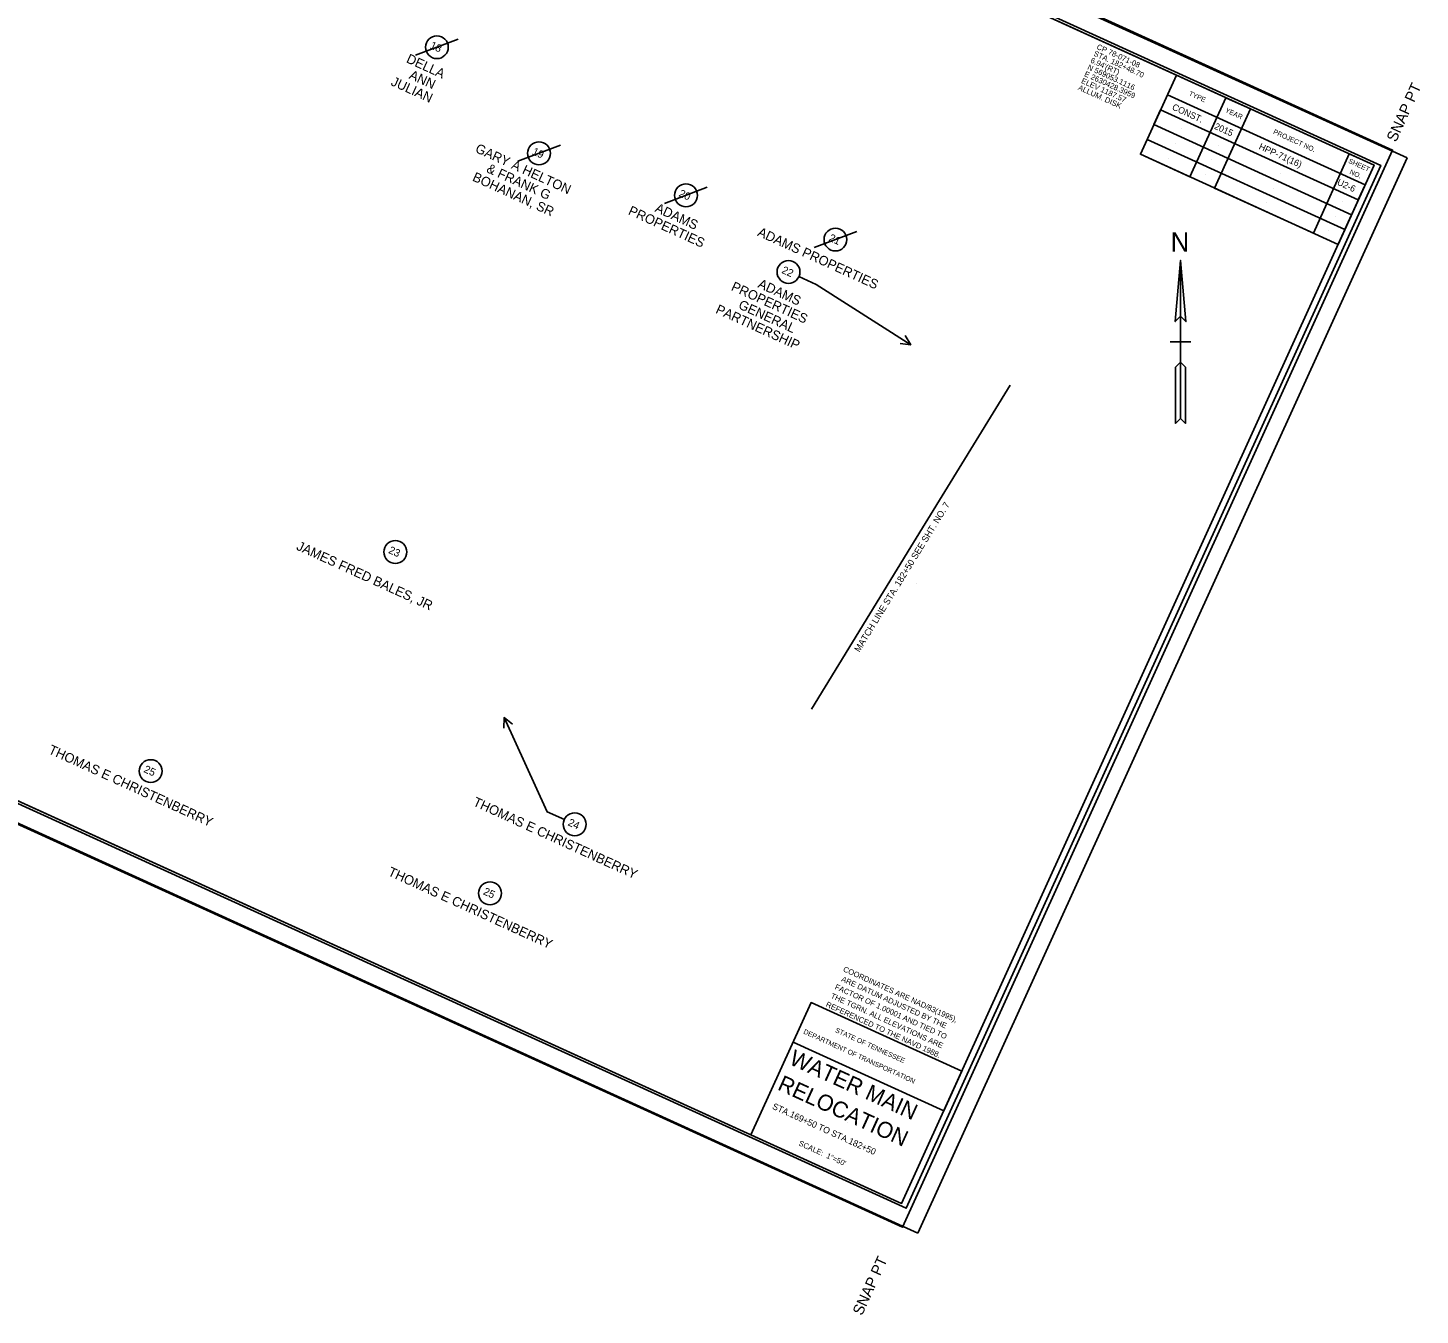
# Model space of a CAD drawing. Extents: x 2628810 to 2630911, y 568379 to 570218.
# Drawn here: x 2629628 to 2630911, y 568379 to 569564 of the extents above; entities that cross this region are included whole.
import ezdxf

# ---------------------------------------------------------------- set-up
doc = ezdxf.new("R2010")
doc.units = 0
for name, color, linetype in [('DESIGN - CENTERLINE - Proposed Text', 7, 'Continuous'), ('DESIGN - SCRATCH - User 1', 7, 'Continuous'), ('DESIGN - SHEET - Corner Text', 7, 'Continuous'), ('DESIGN - SHEET - Light Grid', 7, 'Continuous'), ('DESIGN - SHEET - Linework', 7, 'Continuous'), ('DESIGN - SHEET - Plot Shape', 7, 'Continuous'), ('SURVEY - CONTROL with Text', 7, 'Continuous'), ('SURVEY - PROPERTY - Owners', 7, 'Continuous'), ('SURVEY - PROPERTY - Tract Numbers', 7, 'Continuous')]:
    doc.layers.add(name, color=color, linetype=linetype)

msp = doc.modelspace()

# ---------------------------------------------------------------- linework, layer by layer
at = {"layer": 'DESIGN - CENTERLINE - Proposed Text'}
for p, q in [((2630689.9, 569274.6), (2630680.4, 569274.6)), ((2630699.3, 569274.6), (2630689.9, 569274.6))]:
    msp.add_line(p, q, dxfattribs=at)
for points in [[(2630689.9, 569349.6), (2630685, 569293.3), (2630689.9, 569298.2), (2630694.8, 569293.3), (2630689.9, 569349.6), (2630689.9, 569204.2), (2630694.4, 569199.6), (2630694.4, 569251.4), (2630689.9, 569255.9), (2630685.3, 569251.4), (2630685.3, 569199.6), (2630689.9, 569204.2)], [(2630349.9, 568936.6), (2630441.4, 569085.8), (2630532.9, 569234.9)]]:
    msp.add_lwpolyline(points, dxfattribs=at)
for points in [[(2630689.9, 569298.2), (2630694.8, 569293.3), (2630689.9, 569349.6)], [(2630685.3, 569199.6), (2630689.9, 569204.2), (2630689.9, 569255.9), (2630685.3, 569251.4)]]:
    msp.add_lwpolyline(points, close=True, dxfattribs=at)
at = {"layer": 'DESIGN - SCRATCH - User 1'}
for p, q in [((2630697.4, 569484.7), (2630697.4, 569484.7)), ((2630691.2, 569471.1), (2630691.2, 569471.1)), ((2630731.1, 569469.4), (2630731.1, 569469.4)), ((2630685, 569457.4), (2630685, 569457.4)), ((2630724.9, 569455.7), (2630724.9, 569455.7)), ((2630678.8, 569443.8), (2630678.8, 569443.8)), ((2630718.7, 569442.1), (2630718.7, 569442.1)), ((2630788, 569443.5), (2630788, 569443.5)), ((2630712.4, 569428.4), (2630712.4, 569428.4)), ((2630781.7, 569429.9), (2630781.7, 569429.9)), ((2630775.5, 569416.2), (2630775.5, 569416.2)), ((2630844.8, 569417.6), (2630844.8, 569417.6)), ((2630769.3, 569402.6), (2630769.3, 569402.6)), ((2630838.6, 569404), (2630838.6, 569404)), ((2630832.4, 569390.3), (2630832.4, 569390.3)), ((2630826.2, 569376.7), (2630826.2, 569376.7)), ((2630446.5, 569052.3), (2630446.5, 569052.3)), ((2630383, 568555.8), (2630383, 568555.8))]:
    msp.add_line(p, q, dxfattribs=at)
at = {"layer": 'DESIGN - SHEET - Light Grid'}
msp.add_lwpolyline([(2628921.9, 569166.8), (2630437.2, 568477), (2630874.3, 569437.1), (2629359, 570127)], close=True, dxfattribs=at)
at = {"layer": 'DESIGN - SHEET - Linework'}
for p, q in [((2629260.3, 570189.7), (2630898.6, 569443.9)), ((2630898.6, 569443.9), (2630448, 568454.2)), ((2628809.8, 569200), (2630448, 568454.2))]:
    msp.add_line(p, q, dxfattribs=at)
for points in [[(2629435.3, 570089.5), (2629000.3, 569133.8), (2630433, 568481.6), (2630868.1, 569437.3), (2629435.3, 570089.5)], [(2630686, 569520.1), (2630652.9, 569447.3), (2630834.9, 569364.4), (2630868.1, 569437.3), (2630845.3, 569447.6), (2630812.2, 569374.8), (2630721.2, 569416.2), (2630754.3, 569489), (2630731.6, 569499.4), (2630698.4, 569426.6), (2630652.9, 569447.3), (2630659.1, 569461), (2630841.1, 569378.1), (2630847.4, 569391.7), (2630665.3, 569474.6), (2630671.5, 569488.3), (2630853.6, 569405.4), (2630859.8, 569419.1), (2630677.8, 569501.9)], [(2630294.2, 568544.8), (2630349.6, 568666.4), (2630488.4, 568603.3), (2630471.8, 568566.9), (2630333, 568630)]]:
    msp.add_lwpolyline(points, dxfattribs=at)
at = {"layer": 'DESIGN - SHEET - Plot Shape'}
for points in [[(2629338, 570155.5), (2630885.2, 569451.1), (2630433.8, 568459.6), (2628886.6, 569164)], [(2629357.9, 570124.7), (2630868.1, 569437.3), (2630433, 568481.6), (2628922.9, 569169.1)]]:
    msp.add_lwpolyline(points, close=True, dxfattribs=at)
at = {"layer": 'SURVEY - PROPERTY - Tract Numbers'}
for p, q in [((2629985.3, 569538.5), (2630024.6, 569553.3)), ((2630079.4, 569440.9), (2630118.7, 569455.6)), ((2630214.7, 569402.1), (2630254, 569416.9)), ((2630352.3, 569361.4), (2630391.6, 569376.2))]:
    msp.add_line(p, q, dxfattribs=at)
for points in [[(2630354.3, 569327.4), (2630338.4, 569334.7)], [(2630441.4, 569272), (2630354.3, 569327.4)], [(2630436.4, 569280.4), (2630441.4, 569272), (2630431.7, 569273)], [(2630074.5, 568922.7), (2630066.9, 568928.8), (2630066.5, 568919.1)], [(2630066.9, 568928.8), (2630106.5, 568842.1), (2630122.4, 568834.9)]]:
    msp.add_lwpolyline(points, dxfattribs=at)
for centre in [(2630005, 569545.9), (2630099, 569448.2), (2630234.4, 569409.5), (2630372, 569368.8), (2630328.8, 569339), (2629966.7, 569081.2), (2629741.4, 568879.5), (2630131.9, 568830.5), (2630053.9, 568767)]:
    msp.add_circle(centre, 10.5, dxfattribs=at)

# ---------------------------------------------------------------- texts
at = {"layer": 'DESIGN - CENTERLINE - Proposed Text'}
msp.add_text('N', height=17.7, dxfattribs=at).set_placement((2630680.8, 569357.7))
msp.add_text('MATCH LINE STA. 182+50 SEE SHT. NO. 7', height=6, rotation=58.4832, dxfattribs=at).set_placement((2630394.1, 568988.5))
at = {"layer": 'DESIGN - SHEET - Corner Text'}
for s, height, rotation, p in [('  SNAP PT', 10, 65.5232, (2630885.2, 569451.1)), ('TYPE', 4.5, 335.5232, (2630697.1, 569501.7)), ('CONST.', 6, 335.5232, (2630681.5, 569488.7)), ('YEAR', 4.5, 335.5232, (2630730.5, 569486.3)), ('2015', 6, 335.5232, (2630720.4, 569471)), ('PROJECT NO.', 4.5, 335.5232, (2630774.8, 569466.5)), ('HPP-71(16)', 6, 335.5232, (2630761.4, 569452.3)), ('SHEET', 4.5, 335.5232, (2630844, 569439.6)), ('NO.', 4.5, 335.5232, (2630845.1, 569429.5)), ('U2-6', 6, 335.5232, (2630833.5, 569419.5)), ('ARE DATUM ADJUSTED BY THE', 5, 335.5232, (2630376.9, 568686.3)), ('COORDINATES ARE NAD/83(1995),', 5, 335.5232, (2630378.6, 568695.4)), ('THE TGRN. ALL ELEVATIONS ARE', 5, 335.5232, (2630367.2, 568670.9)), ('FACTOR OF 1.00001 AND TIED TO', 5, 335.5232, (2630371, 568679.1)), ('REFERENCED TO THE NAVD 1988.', 5, 335.5232, (2630362.7, 568663)), ('DEPARTMENT OF TRANSPORTATION', 4.5, 335.5232, (2630342.1, 568638.1)), ('STATE OF TENNESSEE', 4.5, 335.5232, (2630371.4, 568639.4)), ('WATER MAIN', 14.76, 335.5232, (2630328.5, 568610.1)), ('RELOCATION', 14.76, 335.5232, (2630317.8, 568586.6)), ('STA.169+50 TO STA.182+50', 5.906, 335.5232, (2630313.3, 568568.8)), ('SCALE:  1"=50\'', 4.922, 335.5232, (2630337.7, 568535.2)), ('SNAP PT  ', 10, 65.5232, (2630396.5, 568377.7))]:
    msp.add_text(s, height=height, rotation=rotation, dxfattribs=at).set_placement(p)
at = {"layer": 'SURVEY - CONTROL with Text'}
for s, p in [('CP 78-071-08', (2630612.1, 569544.5)), ("6.94'(RT)", (2630606.4, 569532)), ('STA. 182+48.70', (2630609.3, 569538.3)), ('E 2630428.3959', (2630600.7, 569519.5)), ('N 569053.1116', (2630603.6, 569525.7)), ('ALLUM. DISK', (2630595, 569507)), ('ELEV 1187.57', (2630597.9, 569513.2))]:
    msp.add_text(s, height=5, rotation=335.5232, dxfattribs=at).set_placement(p)
at = {"layer": 'SURVEY - PROPERTY - Owners'}
for s, p in [('DELLA', (2629976.1, 569532.2)), ('ANN', (2629978.7, 569517.3)), ('JULIAN', (2629961.9, 569511.2)), ('GARY A HELTON', (2630039.6, 569449.6)), ('& FRANK G', (2630049.9, 569431.2)), ('BOHANAN, SR', (2630037, 569423.3)), ('PROPERTIES', (2630180.5, 569392.3)), ('ADAMS', (2630205.1, 569394.8)), ('ADAMS PROPERTIES', (2630299.6, 569372.6)), ('PROPERTIES', (2630275.3, 569322.5)), ('ADAMS', (2630299.9, 569325)), ('PARTNERSHIP', (2630261, 569301.5)), ('GENERAL', (2630281.9, 569305.7)), ('JAMES FRED BALES, JR', (2629874.9, 569083.6)), ('THOMAS E CHRISTENBERRY', (2629646.5, 568896.1)), ('THOMAS E CHRISTENBERRY', (2630037.5, 568848)), ('THOMAS E CHRISTENBERRY', (2629959.2, 568783.7))]:
    msp.add_text(s, height=8.75, rotation=335.5232, dxfattribs=at).set_placement(p)
at = {"layer": 'SURVEY - PROPERTY - Tract Numbers'}
for s, p in [('18', (2629998, 569545.2)), ('19', (2630092.1, 569447.5)), ('20', (2630227.2, 569408.9)), ('21', (2630365.3, 569368)), ('22', (2630321.9, 569338.3)), ('23', (2629959.8, 569080.5)), ('25', (2629734.4, 568878.8)), ('24', (2630125, 568829.8)), ('25', (2630047, 568766.3))]:
    msp.add_text(s, height=7, rotation=335.5232, dxfattribs=at).set_placement(p)

doc.saveas('drawing.dxf')
